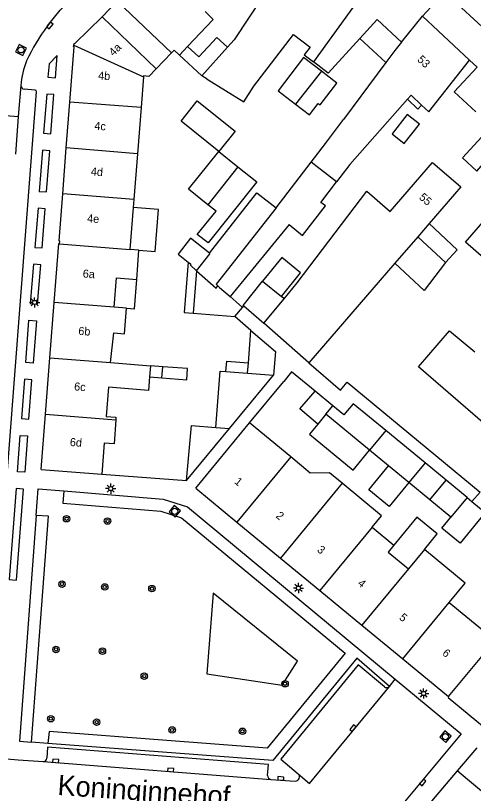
# Model space of a CAD drawing. Extents: x 132573 to 132944, y 398226 to 398676.
# Drawn here: x 132826.8 to 132883.4, y 398341.8 to 398438.1 of the extents above; entities that cross this region are included whole.
import ezdxf

# ---------------------------------------------------------------- set-up
doc = ezdxf.new("R2010")
doc.units = 0
for name, color, linetype in [('gg-afsc-erfafscheiding', 7, 'Continuous'), ('gg-afsc-hekwerk', 7, 'Continuous'), ('gg-afsc-muur', 7, 'Continuous'), ('gg-anno-huisnummerreeks BGT', 7, 'Continuous'), ('gg-anno-openbare ruimte label', 7, 'Continuous'), ('gg-bbg-bijgebouw', 7, 'Continuous'), ('gg-bbg-gedigitaliseerde bebouwing', 7, 'Continuous'), ('gg-bbg-gedigitaliseerde bijgebouw', 7, 'Continuous'), ('gg-bbg-hoofdgebouw', 7, 'Continuous'), ('gg-bbg-luifel en loopbrug', 7, 'Continuous'), ('gg-bbg-onder overbouw', 7, 'Continuous'), ('gg-bbg-pand overbouw', 7, 'Continuous'), ('gg-bbg-tussenscheiding', 7, 'Continuous'), ('gg-knt-verharding', 7, 'Continuous'), ('gg-knt-verharding nz', 7, 'Continuous'), ('gt-grn-groengrens', 7, 'Continuous'), ('gt-symb-boom', 7, 'Continuous'), ('gt-symb-kolk', 7, 'Continuous'), ('gt-symb-lichtmast', 7, 'Continuous'), ('gt-symb-rioolschacht', 7, 'Continuous')]:
    doc.layers.add(name, color=color, linetype=linetype)

msp = doc.modelspace()

# ---------------------------------------------------------------- linework, layer by layer
at = {"layer": 'gg-afsc-erfafscheiding'}
for p, q in [((132854.853, 398401.965), (132855.002, 398402.137)), ((132855.883, 398399.104), (132853.877, 398400.833))]:
    msp.add_line(p, q, dxfattribs=at)
for points in [[(132863.045, 398395.109), (132866.966, 398391.729), (132867.783, 398392.696), (132884.262, 398379.11), (132883.243, 398377.928)], [(132863.839, 398391.587), (132860.923, 398393.993), (132859.939, 398392.799)]]:
    msp.add_lwpolyline(points, dxfattribs=at)
at = {"layer": 'gg-afsc-hekwerk'}
msp.add_line((132883.894, 398431.693), (132882.94, 398432.54), dxfattribs=at)
at = {"layer": 'gg-afsc-muur'}
for p, q in [((132855.703, 398387.664), (132859.939, 398392.799)), ((132837.422, 398381.312), (132847.901, 398380.538))]:
    msp.add_line(p, q, dxfattribs=at)
at = {"layer": 'gg-bbg-bijgebouw'}
for p, q in [((132853.235, 398386.976), (132858.692, 398393.562)), ((132847.901, 398380.538), (132853.235, 398386.976))]:
    msp.add_line(p, q, dxfattribs=at)
at = {"layer": 'gg-bbg-gedigitaliseerde bebouwing'}
for p, q in [((132871.491, 398437.569), (132869.357, 398435.234)), ((132871.491, 398437.569), (132874.527, 398434.767)), ((132846.034, 398433.434), (132846.365, 398433.78)), ((132847.035, 398433.163), (132846.365, 398433.78)), ((132872.589, 398432.251), (132867.324, 398425.188)), ((132877.911, 398426.136), (132882.94, 398432.54)), ((132842.586, 398430.489), (132842.288, 398426.682)), ((132850.474, 398430.186), (132849.826, 398430.589)), ((132842.288, 398426.682), (132841.842, 398420.976)), ((132877.911, 398426.136), (132877.009, 398426.987)), ((132841.842, 398420.976), (132841.398, 398415.293)), ((132841.398, 398415.293), (132841.321, 398414.302)), ((132841.321, 398414.302), (132840.917, 398409.141)), ((132877.948, 398412.333), (132876.536, 398410.701)), ((132842.025, 398409.054), (132840.917, 398409.141)), ((132841.745, 398405.41), (132842.025, 398409.054)), ((132873.696, 398407.418), (132863.045, 398395.109)), ((132857.485, 398399.996), (132859.991, 398403.031)), ((132840.486, 398401.869), (132838.961, 398401.987)), ((132863.045, 398395.109), (132857.485, 398399.996)), ((132838.518, 398395.123), (132838.909, 398398.798)), ((132838.518, 398395.123), (132843.437, 398394.743)), ((132860.804, 398383.456), (132855.703, 398387.664)), ((132870.875, 398374.761), (132873.577, 398372.534)), ((132873.577, 398372.534), (132872.87, 398371.676)), ((132872.87, 398371.676), (132875.368, 398369.617)), ((132877.352, 398372.02), (132875.368, 398369.617)), ((132880.436, 398365.438), (132886.1, 398360.77))]:
    msp.add_line(p, q, dxfattribs=at)
for points in [[(132865.947, 398442.685), (132862.841, 398439.321), (132858.972, 398442.892), (132853.795, 398435.076), (132852.967, 398434.14)], [(132850.217, 398438.558), (132851.224, 398437.577), (132848.049, 398434.231)], [(132850.474, 398430.186), (132854.986, 398427.379), (132856.247, 398429.349), (132861.162, 398435.742), (132863.215, 398434.163), (132862.483, 398433.212), (132863.633, 398432.327)], [(132869.357, 398435.234), (132865.435, 398430.941), (132863.633, 398432.327)], [(132874.527, 398434.767), (132873.695, 398433.734), (132872.589, 398432.251)], [(132844.172, 398431.472), (132843.261, 398430.52), (132842.594, 398430.593), (132842.586, 398430.489)], [(132883.894, 398431.693), (132881.052, 398428.627), (132883.711, 398426.159)], [(132877.009, 398426.987), (132875.705, 398428.216), (132875.264, 398427.717)], [(132875.264, 398427.717), (132868.121, 398419.623), (132866.496, 398417.503)], [(132863.347, 398419.917), (132865.113, 398422.222), (132867.324, 398425.188)], [(132859.991, 398403.031), (132861.626, 398405.01), (132870.249, 398416.336), (132873.103, 398413.828), (132878.359, 398419.902), (132881.87, 398416.865), (132877.948, 398412.333)], [(132901.436, 398410.869), (132897.968, 398414.103), (132895.649, 398411.617), (132894.918, 398412.299), (132888.54, 398404.712), (132882.424, 398410.022), (132885.915, 398414.043)], [(132838.961, 398401.987), (132839.238, 398405.602), (132841.745, 398405.41)], [(132838.909, 398398.798), (132840.243, 398398.696), (132840.486, 398401.869)], [(132843.33, 398393.361), (132843.201, 398391.687), (132838.251, 398392.086)], [(132867.191, 398380.197), (132865.622, 398381.492), (132863.226, 398381.457), (132860.804, 398383.456)], [(132870.875, 398374.761), (132872.051, 398376.186), (132867.191, 398380.197)], [(132880.436, 398365.438), (132882.418, 398367.841), (132877.352, 398372.02)]]:
    msp.add_lwpolyline(points, dxfattribs=at)
at = {"layer": 'gg-bbg-gedigitaliseerde bijgebouw'}
for p, q in [((132849.826, 398430.589), (132847.035, 398433.163)), ((132851.922, 398421.252), (132854.273, 398419.366)), ((132858.99, 398414.284), (132863.347, 398419.917)), ((132860.605, 398412.203), (132853.302, 398403.302)), ((132876.536, 398410.701), (132879.955, 398407.512)), ((132849.151, 398406.501), (132848.743, 398401.23)), ((132857.313, 398405.189), (132859.652, 398403.304)), ((132848.743, 398401.23), (132853.877, 398400.833)), ((132853.877, 398400.833), (132854.853, 398401.965)), ((132855.574, 398395.118), (132855.883, 398399.104)), ((132844.975, 398394.624), (132843.437, 398394.743)), ((132844.869, 398393.243), (132844.975, 398394.624)), ((132855.473, 398393.811), (132855.574, 398395.118)), ((132852.782, 398394.019), (132855.473, 398393.811)), ((132843.33, 398393.361), (132844.869, 398393.243)), ((132866.026, 398389.784), (132863.839, 398391.587)), ((132865.173, 398388.751), (132864.149, 398387.51)), ((132870.573, 398384.297), (132865.173, 398388.751)), ((132877.437, 398382.716), (132872.577, 398386.725)), ((132872.92, 398382.361), (132870.573, 398384.297)), ((132875.434, 398380.287), (132872.92, 398382.361)), ((132877.437, 398382.716), (132875.434, 398380.287)), ((132878.033, 398378.143), (132880.036, 398380.572)), ((132882.637, 398378.427), (132880.036, 398380.572)), ((132880.633, 398375.999), (132878.033, 398378.143)), ((132882.637, 398378.427), (132883.243, 398377.928))]:
    msp.add_line(p, q, dxfattribs=at)
for points in [[(132848.049, 398434.231), (132849.422, 398432.965), (132851.671, 398435.335), (132852.967, 398434.14)], [(132851.922, 398421.252), (132847.242, 398425.005), (132849.244, 398427.502), (132853.924, 398423.748), (132851.922, 398421.252)], [(132850.554, 398414.658), (132848.169, 398416.571), (132851.922, 398421.252)], [(132854.273, 398419.366), (132856.603, 398417.498), (132850.599, 398409.959), (132849.229, 398410.972), (132851.564, 398413.848), (132850.554, 398414.658)], [(132860.605, 398412.203), (132862.26, 398410.846), (132865.099, 398414.516), (132864.525, 398414.955), (132866.496, 398417.503)], [(132850.765, 398408.663), (132856.63, 398416.136), (132858.99, 398414.284)], [(132850.765, 398408.663), (132848.405, 398410.515), (132846.861, 398408.548), (132848.115, 398407.564)], [(132859.652, 398403.304), (132862.027, 398406.251), (132859.689, 398408.136), (132857.313, 398405.189)], [(132848.115, 398407.564), (132848.409, 398407.333), (132848.397, 398407.175), (132849.151, 398406.501)], [(132879.955, 398407.512), (132877.317, 398404.032), (132873.696, 398407.418)], [(132854.853, 398401.965), (132854.049, 398402.658), (132853.302, 398403.302)], [(132855.883, 398399.104), (132858.917, 398396.488), (132858.692, 398393.562)], [(132891.771, 398388.035), (132888.559, 398384.309), (132876.639, 398394.585), (132880.479, 398399.04), (132883.608, 398396.451)], [(132851.547, 398387.106), (132852.086, 398394.073), (132852.782, 398394.019)], [(132864.149, 398387.51), (132861.955, 398389.401), (132863.839, 398391.587)], [(132872.577, 398386.725), (132868.55, 398390.046), (132867.4, 398388.651), (132866.026, 398389.784)], [(132847.901, 398380.538), (132848.528, 398387.34), (132851.547, 398387.106)], [(132883.243, 398377.928), (132884.878, 398376.579), (132881.764, 398372.802), (132879.522, 398374.651), (132880.633, 398375.999)]]:
    msp.add_lwpolyline(points, dxfattribs=at)
at = {"layer": 'gg-bbg-hoofdgebouw'}
for p, q in [((132877.14, 398438.01), (132879.866, 398440.959)), ((132882.94, 398432.54), (132877.14, 398438.01)), ((132833.029, 398421.684), (132833.467, 398427.343)), ((132832.589, 398416.002), (132833.029, 398421.684)), ((132831.01, 398395.704), (132831.542, 398402.561)), ((132830.469, 398388.737), (132831.01, 398395.704)), ((132829.94, 398381.91), (132830.469, 398388.737)), ((132849.06, 398379.61), (132855.703, 398387.664)), ((132829.94, 398381.91), (132837.422, 398381.312)), ((132849.06, 398379.61), (132854.159, 398375.404)), ((132854.159, 398375.404), (132859.561, 398370.948)), ((132859.561, 398370.948), (132864.423, 398366.938)), ((132864.423, 398366.938), (132869.622, 398362.649)), ((132869.622, 398362.649), (132874.687, 398358.471)), ((132880.35, 398353.8), (132886.1, 398360.77)), ((132874.687, 398358.471), (132880.35, 398353.8)), ((132883.843, 398347.481), (132881.424, 398344.622)), ((132881.424, 398344.622), (132877.328, 398339.782))]:
    msp.add_line(p, q, dxfattribs=at)
for points in [[(132833.954, 398434.382), (132833.99, 398434.611), (132834.089, 398434.596), (132837.455, 398437.904)], [(132833.467, 398427.343), (132833.998, 398434.213), (132833.929, 398434.218), (132833.954, 398434.382)], [(132832.207, 398409.842), (132832.231, 398410.162), (132832.14, 398410.192), (132832.589, 398416.002)], [(132831.542, 398402.561), (132832.107, 398409.85), (132832.207, 398409.842)], [(132838.251, 398392.086), (132837.959, 398388.463), (132839.173, 398388.365), (132839.153, 398388.065)], [(132839.153, 398388.065), (132838.953, 398385.086), (132837.704, 398385.16), (132837.422, 398381.312)]]:
    msp.add_lwpolyline(points, dxfattribs=at)
at = {"layer": 'gg-bbg-luifel en loopbrug'}
for p, q in [((132869.357, 398435.234), (132872.589, 398432.251)), ((132864.608, 398431.191), (132861.389, 398427.106)), ((132877.948, 398412.333), (132881.426, 398409.089)), ((132881.426, 398409.089), (132879.955, 398407.512)), ((132859.991, 398403.031), (132859.652, 398403.304)), ((132855.002, 398402.137), (132857.485, 398399.996)), ((132880.036, 398380.572), (132877.437, 398382.716)), ((132878.033, 398378.143), (132875.434, 398380.287))]:
    msp.add_line(p, q, dxfattribs=at)
for points in [[(132864.608, 398431.191), (132862.409, 398432.883), (132859.238, 398428.761), (132861.389, 398427.106)], [(132861.389, 398427.106), (132863.121, 398425.773), (132864.219, 398427.2), (132864.457, 398427.017), (132866.53, 398429.712), (132864.608, 398431.191)], [(132875.264, 398427.717), (132876.552, 398426.502), (132877.009, 398426.987)], [(132873.348, 398423.432), (132874.857, 398422.247), (132876.729, 398424.631), (132875.22, 398425.816), (132873.348, 398423.432)], [(132884.933, 398423.571), (132882.053, 398420.469), (132883.835, 398418.814), (132886.624, 398422), (132884.933, 398423.571)], [(132842.025, 398409.054), (132844.047, 398408.891), (132844.451, 398414.05), (132841.321, 398414.302)], [(132848.115, 398407.564), (132847.632, 398401.316), (132848.743, 398401.23)], [(132840.486, 398401.869), (132841.467, 398401.793), (132841.745, 398405.41)], [(132855.002, 398402.137), (132854.914, 398402.213), (132857.313, 398405.189)], [(132852.782, 398394.019), (132852.883, 398395.326), (132855.574, 398395.118)], [(132844.869, 398393.243), (132847.935, 398393.006), (132848.041, 398394.387), (132844.975, 398394.624)], [(132864.149, 398387.51), (132863.136, 398386.283), (132868.536, 398381.828), (132870.573, 398384.297)], [(132875.434, 398380.287), (132872.977, 398377.31), (132870.464, 398379.384), (132872.92, 398382.361)], [(132877.352, 398372.02), (132878.928, 398373.93), (132876.428, 398375.991), (132873.577, 398372.534)]]:
    msp.add_lwpolyline(points, dxfattribs=at)
at = {"layer": 'gg-bbg-onder overbouw'}
for p, q in [((132846.034, 398433.434), (132839.317, 398439.866)), ((132837.455, 398437.904), (132844.172, 398431.472))]:
    msp.add_line(p, q, dxfattribs=at)
at = {"layer": 'gg-bbg-pand overbouw'}
for p, q in [((132839.317, 398439.866), (132837.455, 398437.904)), ((132844.172, 398431.472), (132846.034, 398433.434))]:
    msp.add_line(p, q, dxfattribs=at)
at = {"layer": 'gg-bbg-tussenscheiding'}
for p, q in [((132869.048, 398439.823), (132863.633, 398432.327)), ((132874.527, 398434.767), (132877.14, 398438.01)), ((132833.954, 398434.382), (132842.586, 398430.489)), ((132848.049, 398434.231), (132847.035, 398433.163)), ((132852.967, 398434.14), (132849.826, 398430.589)), ((132842.288, 398426.682), (132833.467, 398427.343)), ((132841.842, 398420.976), (132833.029, 398421.684)), ((132866.496, 398417.503), (132863.347, 398419.917)), ((132854.273, 398419.366), (132850.554, 398414.658)), ((132841.398, 398415.293), (132832.589, 398416.002)), ((132832.207, 398409.842), (132840.917, 398409.141)), ((132876.536, 398410.701), (132873.696, 398407.418)), ((132838.961, 398401.987), (132831.542, 398402.561)), ((132831.01, 398395.704), (132838.518, 398395.123)), ((132843.437, 398394.743), (132843.33, 398393.361)), ((132855.473, 398393.811), (132858.692, 398393.562)), ((132865.173, 398388.751), (132866.026, 398389.784)), ((132830.469, 398388.737), (132839.153, 398388.065)), ((132851.547, 398387.106), (132853.235, 398386.976)), ((132872.577, 398386.725), (132870.573, 398384.297)), ((132860.804, 398383.456), (132854.159, 398375.404)), ((132867.191, 398380.197), (132859.561, 398370.948)), ((132882.637, 398378.427), (132880.633, 398375.999)), ((132870.875, 398374.761), (132864.423, 398366.938)), ((132875.368, 398369.617), (132869.622, 398362.649)), ((132874.687, 398358.471), (132880.436, 398365.438)), ((132888.246, 398338.849), (132881.424, 398344.622))]:
    msp.add_line(p, q, dxfattribs=at)
for points in [[(132858.99, 398414.284), (132851.582, 398404.844), (132851.804, 398404.621)], [(132849.151, 398406.501), (132850.836, 398408.607), (132850.765, 398408.663)], [(132849.151, 398406.501), (132851.582, 398404.327), (132851.804, 398404.621)], [(132851.804, 398404.621), (132851.996, 398404.428), (132853.302, 398403.302)]]:
    msp.add_lwpolyline(points, dxfattribs=at)
at = {"layer": 'gg-knt-verharding'}
for p, q in [((132824.644, 398367.756), (132829.363, 398428.64)), ((132829.17, 398428.849), (132827.83, 398428.957)), ((132830.619, 398428.358), (132830.228, 398423.511)), ((132822.089, 398425.934), (132827.093, 398425.596)), ((132827.093, 398425.596), (132826.738, 398420.929)), ((132830.228, 398423.511), (132831.124, 398423.427)), ((132830.59, 398416.253), (132830.982, 398421.341)), ((132829.66, 398416.314), (132830.59, 398416.253)), ((132830.054, 398409.309), (132830.429, 398414.147)), ((132829.133, 398409.365), (132830.054, 398409.309)), ((132829.486, 398402.348), (132829.87, 398407.236)), ((132828.576, 398402.451), (132829.486, 398402.348)), ((132829.329, 398400.281), (132828.918, 398395.065)), ((132828.376, 398388.147), (132828.783, 398392.983)), ((132827.47, 398388.212), (132828.376, 398388.147)), ((132828.23, 398386.053), (132827.886, 398381.555)), ((132829.319, 398376.203), (132829.566, 398379.504)), ((132829.566, 398379.504), (132832.712, 398379.249)), ((132829.319, 398376.203), (132827.226, 398348.276)), ((132873.024, 398355.072), (132873.743, 398355.982)), ((132873.743, 398355.982), (132881.896, 398349.211)), ((132881.896, 398349.211), (132873.641, 398339.288)), ((132827.226, 398348.276), (132828.722, 398348.162)), ((132830.757, 398348.006), (132828.722, 398348.162)), ((132824.691, 398346.18), (132827.083, 398345.999)), ((132827.083, 398345.999), (132830.158, 398345.767)), ((132858.346, 398343.563), (132861.354, 398343.353))]:
    msp.add_line(p, q, dxfattribs=at)
for points in [[(132830.702, 398436.785), (132832.286, 398438.714), (132841.442, 398448.172)], [(132886.627, 398434.629), (132885.53, 398435.616), (132885.581, 398435.671), (132885.532, 398435.717), (132879.866, 398440.959)], [(132831.909, 398433.116), (132830.898, 398432.102), (132830.744, 398430.451), (132831.687, 398430.373), (132831.909, 398433.116)], [(132831.124, 398423.427), (132831.477, 398428.278), (132830.619, 398428.358)], [(132830.982, 398421.341), (132830.071, 398421.419), (132829.66, 398416.314)], [(132830.429, 398414.147), (132829.541, 398414.215), (132829.133, 398409.365)], [(132829.87, 398407.236), (132828.965, 398407.309), (132828.576, 398402.451)], [(132828.918, 398395.065), (132828.013, 398395.141), (132828.409, 398400.366), (132829.329, 398400.281)], [(132828.783, 398392.983), (132827.87, 398393.064), (132827.47, 398388.212)], [(132827.886, 398381.555), (132826.978, 398381.63), (132827.31, 398386.122), (132828.23, 398386.053)], [(132827.73, 398379.475), (132826.825, 398379.543), (132825.967, 398368.308)], [(132825.967, 398368.308), (132826.866, 398368.221), (132827.73, 398379.475)], [(132832.712, 398379.249), (132845.039, 398378.249), (132848.015, 398377.271), (132873.743, 398355.982)], [(132873.024, 398355.072), (132868.982, 398358.541), (132858.577, 398345.883), (132830.757, 398348.006)], [(132872.398, 398355.021), (132869.17, 398357.738), (132859.584, 398346.08), (132861.736, 398344.248)], [(132880.35, 398353.8), (132880.276, 398353.71), (132885.477, 398349.412)], [(132857.935, 398344.063), (132858.075, 398345.422), (132830.716, 398347.555), (132830.644, 398346.186)]]:
    msp.add_lwpolyline(points, dxfattribs=at)
for centre, radius, start, end in [((132849.044, 398422.948), 22.976, 142.97023, 155.56619), ((132837.103, 398428.748), 9.711, 157.57974, 175.96882), ((132827.902, 398429.438), 0.486, 180.81664, 261.45243), ((132829.142, 398428.629), 0.221, 2.73073, 82.71081), ((132872.685, 398355.364), 0.447, 230.07755, 319.23761), ((132830.167, 398346.248), 0.481, 268.96776, 352.56412), ((132858.403, 398344.029), 0.469, 175.82041, 263.02), ((132861.39, 398343.867), 0.515, 266.04262, 47.73029)]:
    msp.add_arc(centre, radius, start, end, dxfattribs=at)
at = {"layer": 'gg-knt-verharding nz'}
for p, q in [((132827.416, 398429.431), (132827.093, 398425.596)), ((132830.158, 398345.767), (132858.346, 398343.563))]:
    msp.add_line(p, q, dxfattribs=at)
msp.add_lwpolyline([(132861.736, 398344.248), (132863.151, 398343.059), (132873.024, 398355.072)], dxfattribs=at)
at = {"layer": 'gt-grn-groengrens'}
for points in [[(132832.712, 398379.249), (132832.598, 398377.751), (132844.74, 398376.768), (132847.277, 398375.935), (132867.549, 398359.16), (132857.913, 398347.438), (132830.893, 398349.5), (132830.757, 398348.006)], [(132828.722, 398348.162), (132830.817, 398376.119), (132829.319, 398376.203)], [(132850.41, 398356.616), (132859.742, 398355.225), (132861.653, 398358.187), (132851.226, 398366.611), (132850.41, 398356.616)]]:
    msp.add_lwpolyline(points, dxfattribs=at)
at = {"layer": 'gt-symb-boom'}
for centre, radius in [((132833.067, 398375.81), 0.4), ((132833.067, 398375.81), 0.2), ((132838.139, 398375.524), 0.4), ((132838.139, 398375.524), 0.2), ((132832.502, 398367.722), 0.4), ((132832.502, 398367.722), 0.2), ((132837.788, 398367.374), 0.4), ((132837.788, 398367.374), 0.2), ((132843.633, 398367.171), 0.4), ((132843.633, 398367.171), 0.2), ((132831.757, 398359.639), 0.4), ((132831.757, 398359.639), 0.2), ((132837.503, 398359.433), 0.4), ((132837.503, 398359.433), 0.2), ((132842.682, 398356.338), 0.4), ((132842.682, 398356.338), 0.2), ((132860.11, 398355.394), 0.4), ((132860.11, 398355.394), 0.2), ((132831.116, 398351.072), 0.4), ((132831.116, 398351.072), 0.2), ((132836.788, 398350.644), 0.4), ((132836.788, 398350.644), 0.2), ((132846.133, 398349.676), 0.4), ((132846.133, 398349.676), 0.2), ((132854.837, 398349.516), 0.4), ((132854.837, 398349.516), 0.2)]:
    msp.add_circle(centre, radius, dxfattribs=at)
at = {"layer": 'gt-symb-kolk'}
for points in [[(132830.841, 398436.964), (132830.611, 398436.668), (132830.927, 398436.423), (132831.387, 398437.015), (132831.071, 398437.26), (132830.841, 398436.964)], [(132868.663, 398349.763), (132868.901, 398350.053), (132868.592, 398350.307), (132868.116, 398349.727), (132868.425, 398349.473), (132868.663, 398349.763)], [(132831.714, 398345.652), (132832.088, 398345.624), (132832.118, 398346.023), (132831.37, 398346.079), (132831.34, 398345.68), (132831.714, 398345.652)], [(132845.927, 398344.536), (132846.301, 398344.507), (132846.332, 398344.906), (132845.584, 398344.964), (132845.553, 398344.565), (132845.927, 398344.536)], [(132859.573, 398343.475), (132859.947, 398343.448), (132859.976, 398343.847), (132859.228, 398343.901), (132859.199, 398343.502), (132859.573, 398343.475)], [(132876.993, 398343.322), (132876.753, 398343.034), (132877.061, 398342.778), (132877.54, 398343.354), (132877.233, 398343.61), (132876.993, 398343.322)]]:
    msp.add_lwpolyline(points, dxfattribs=at)
at = {"layer": 'gt-symb-lichtmast'}
for p, q in [((132828.935, 398402.753), (132828.67, 398403.018)), ((132829.112, 398402.826), (132829.112, 398403.201)), ((132829.289, 398402.753), (132829.554, 398403.018)), ((132828.862, 398402.576), (132828.487, 398402.576)), ((132828.935, 398402.399), (132828.67, 398402.134)), ((132829.112, 398402.326), (132829.112, 398401.951)), ((132829.554, 398402.134), (132829.289, 398402.399)), ((132829.362, 398402.576), (132829.737, 398402.576)), ((132838.351, 398379.713), (132838.086, 398379.978)), ((132838.528, 398379.786), (132838.528, 398380.161)), ((132838.705, 398379.713), (132838.97, 398379.978)), ((132838.278, 398379.536), (132837.903, 398379.536)), ((132838.351, 398379.359), (132838.086, 398379.094)), ((132838.528, 398379.286), (132838.528, 398378.911)), ((132838.97, 398379.094), (132838.705, 398379.359)), ((132838.778, 398379.536), (132839.153, 398379.536)), ((132861.588, 398367.415), (132861.323, 398367.68)), ((132861.765, 398367.488), (132861.765, 398367.863)), ((132861.942, 398367.415), (132862.207, 398367.68)), ((132861.515, 398367.238), (132861.14, 398367.238)), ((132861.588, 398367.061), (132861.323, 398366.796)), ((132861.765, 398366.988), (132861.765, 398366.613)), ((132862.207, 398366.796), (132861.942, 398367.061)), ((132862.015, 398367.238), (132862.39, 398367.238)), ((132877.012, 398354.188), (132876.637, 398354.188)), ((132877.085, 398354.365), (132876.82, 398354.63)), ((132877.085, 398354.011), (132876.82, 398353.746)), ((132877.262, 398354.438), (132877.262, 398354.813)), ((132877.262, 398353.938), (132877.262, 398353.563)), ((132877.439, 398354.365), (132877.704, 398354.63)), ((132877.704, 398353.746), (132877.439, 398354.011)), ((132877.512, 398354.188), (132877.887, 398354.188))]:
    msp.add_line(p, q, dxfattribs=at)
for centre in [(132829.112, 398402.576), (132838.528, 398379.536), (132861.765, 398367.238), (132877.262, 398354.188)]:
    msp.add_circle(centre, 0.25, dxfattribs=at)
at = {"layer": 'gt-symb-rioolschacht'}
for points in [[(132827.188, 398434.473), (132826.764, 398433.567), (132827.67, 398433.143), (132828.094, 398434.049)], [(132847.157, 398376.796), (132846.385, 398377.432), (132845.749, 398376.66), (132846.521, 398376.024)], [(132879.903, 398349.551), (132879.249, 398348.795), (132880.005, 398348.141), (132880.659, 398348.897)]]:
    msp.add_lwpolyline(points, close=True, dxfattribs=at)
for centre in [(132827.429, 398433.808), (132846.453, 398376.728), (132879.954, 398348.846)]:
    msp.add_circle(centre, 0.375, dxfattribs=at)

# ---------------------------------------------------------------- texts
at = {"layer": 'gg-anno-huisnummerreeks BGT'}
for s, rotation, p in [('4a', 44.5, (132838.874, 398432.988)), ('53', 316.7, (132876.397, 398432.525)), ('4b', 355.6, (132836.947, 398430.181)), ('4c', 355.6, (132836.483, 398423.954)), ('4d', 355.6, (132836.05, 398418.302)), ('55', 319.1, (132876.618, 398415.458)), ('4e', 355.6, (132835.579, 398412.5)), ('6a', 355.6, (132835.045, 398405.663)), ('6b', 355.6, (132834.494, 398398.571)), ('6c', 355.6, (132833.977, 398391.697)), ('6d', 355.6, (132833.449, 398384.819)), ('1', 320.5, (132853.764, 398380.266)), ('2', 320.5, (132858.886, 398376.042)), ('3', 320.5, (132863.989, 398371.833)), ('4', 320.5, (132869.023, 398367.68)), ('5', 320.5, (132874.149, 398363.451)), ('6', 320.5, (132879.489, 398359.047))]:
    msp.add_text(s, height=1, rotation=rotation, dxfattribs=at).set_placement(p)
at = {"layer": 'gg-anno-openbare ruimte label'}
msp.add_text('Koninginnehof', height=2.5, rotation=356.1, dxfattribs=at).set_placement((132831.897, 398341.642))

doc.saveas('drawing.dxf')
